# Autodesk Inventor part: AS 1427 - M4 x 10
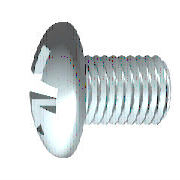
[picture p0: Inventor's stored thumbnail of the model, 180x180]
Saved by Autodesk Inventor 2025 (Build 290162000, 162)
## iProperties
Created: 2024-01
Part Number: AS 1427 - M4 x 10
Material: Acciaio, Dolce
Description: Pozidriv Viti metriche ISO
Document SubType Name: Modeling
Standard: AS 1427
Designer: R5800u
Standards Organization: AS
Language: it-IT
Size Designation: M4 x 10
Categories: <MemberInstance><Categories><Category DisplayName="Elementi di fissaggio" InternalName="e4da775c-781d-43d5-af7c-5136215cf5a6" Mnemonic="FSTN"><Category DisplayN
Density: 7.85 g/cm^3
Appearance: Semilucidato
IsCustomPart: 0
Author: R5800u
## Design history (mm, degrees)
body "Solid1"
workplane "Work Plane3"
sketch "Schizzo2"
  geometry: L1 (-5.6, 0)-(5.6, 0) reference; L2 (0, -5.6)-(0, 5.6) reference; L3 (0, 2.145)-(0, 0); L4 (0, 0)-(2.145, 0); L5 (0, 0)-(2.828, 2.828); L6 (0.495, 2.087)-(0.385, 0.645); L7 (2.087, 0.495)-(0.645, 0.385); L8 (0.495, -2.087)-(0.385, -0.645); L9 (2.087, -0.495)-(0.645, -0.385); L10 (-0.495, 2.087)-(-0.385, 0.645); L11 (-2.087, 0.495)-(-0.645, 0.385); L12 (-2.087, -0.495)-(-0.645, -0.385); L13 (-0.495, -2.087)-(-0.385, -0.645); A1 r 0.644 centre (0, 0) between (0.644, 0) and (0, 0.644); A2 r 2.145 centre (0, 0) between (2.145, 0) and (2.087, 0.495); A3 r 2.145 centre (0, 0) between (0.495, 2.087) and (0, 2.145); A4 r 2.145 centre (0, 0) between (2.087, 0.495) and (0.495, 2.087); A5 r 2.145 centre (0, 0) between (0, -2.145) and (0.495, -2.087); A6 r 2.145 centre (0, 0) between (0.495, -2.087) and (2.087, -0.495); A7 r 2.145 centre (0, 0) between (2.087, -0.495) and (2.145, 0); A8 r 2.145 centre (0, 0) between (-2.087, 0.495) and (-2.145, 0); A9 r 2.145 centre (0, 0) between (-0.495, 2.087) and (-2.087, 0.495); A10 r 2.145 centre (0, 0) between (0, 2.145) and (-0.495, 2.087); A11 r 2.145 centre (0, 0) between (-2.145, 0) and (-2.087, -0.495); A12 r 2.145 centre (0, 0) between (-2.087, -0.495) and (-0.495, -2.087); A13 r 2.145 centre (0, 0) between (-0.495, -2.087) and (0, -2.145); A14 r 0.751 centre (0, 0) between (0.751, 0) and (0, 0.751); A15 r 0.242 centre (0.626, 0.626) between (0.385, 0.645) and (0.645, 0.385); A16 r 0.242 centre (0.626, -0.626) between (0.645, -0.385) and (0.385, -0.645); A17 r 0.242 centre (-0.626, 0.626) between (-0.645, 0.385) and (-0.385, 0.645); A18 r 0.242 centre (-0.626, -0.626) between (-0.385, -0.645) and (-0.645, -0.385); 1 further point
  constraints: 38 point on circle, 22 end point, 19 symmetric about line, 18 centre point, 4 coincident, 3 collinear, 3 point on line, 3 tangent, 1 perpendicular, 21 other
  dimensions: "d4" = 45 deg angle of L5 L4; "d5" = 1.287 diameter of A1 (= 0.3 x SDM); "d6" = 4.29 diameter of A4 (= SDM); "d7" = 0.495 distance from line of L6.start L3 (= 0.5 x SBR); "d14" = 1.5015 diameter of A14 (= 0.35 x SDM)
extrude "Intaglio" join sketch "Schizzo2" taper "d15" = 5 deg; stored distance "d54" = 10
revolve "Taglio" stored, may be unused: angle "d56" = 90 deg
revolve "Corpo" stored, may be unused: angle "d18" = 90 deg
workplane "Work Plane1"
sketch "Schizzo1"
  geometry: L1 (10, 0)-(10, 2); L2 (10, 2)-(1.4, 2); L3 (3.962, 5.08)-(3.962, 5.08); L4 (-2.66, 0)-(-2.66, 4); L5 (-2.334, 1.983)-(-1.654, 1.643); L6 (-1.654, 1.643)-(-0.78, 0); L7 (-0.78, 0)-(10, 0); L8 (-5.617, 0)-(12.603, 0) reference; L9 (0, -1.016)-(0, 6.096) reference; L10 (-2.334, 1.983)-(-2.66, 2.145); L11 (-1.197, 4)-(-2.66, 4); L12 (-1.197, 4)-(0, 4); L13 (0, 4)-(0, 1.785); L14 (0, 1.785)-(0.971, 1.785); L15 (0.971, 1.785)-(1.4, 2); L16 (1.4, 2)-(0, 2); A1 r 6.2 centre (3.54, 0) between (-1.197, 4) and (-2.66, 0)
  constraints: 28 end point, 5 point on line, 4 collinear, 4 point on circle, 3 parallel, 2 perpendicular, 1 centre point, 1 horizontal, 1 tangent
  dimensions: "d1" = 4 diameter of L2 L7 (= GD); "d2" = 1.88 distance from line of L6.end L4 (= STI); "d11" = 4.29 diameter of L10.end L7 (= SDM); "d12" = 62 deg angle of L6 L7; "d13" = 26.5 deg angle of L5 L7; "d17" = 8 diameter of L12.end L7 (= KOD); "d19" = 0.01 deg angle of L12 L7 (= KEWI); "d20" = 2.66 distance between parallel lines of L4 L13 (= KOH); "d21" = 6.2 radius of A1 (= KR); "d23" = 3.5705 diameter of L14 L7 (= BDM); "d24" = 8.6 distance of L1.end L2.end (= GEL); "d25" = 0.42941 horizontal distance of L14.end L2.end (= GAL); "d28" = 10 distance between parallel lines of L1 L13 (= NLG)
fillet "Raccordo1" dims "d29" = 1.6 (= RR)
fillet "Raccordo2" dims "d16" = 0.198 (= 0.2 x SBR)
feature "Filettatura" dims "d8" = 8.6 (= GEL), "d9" = 0
chamfer "Smusso1" distance "d26" = 0.42941 (= -0.5 x SPD + 0.5 x GD); stored, may be unused: second distance "d27" = 0.42952 (computed from GUL), angle "d78" = 45 deg
other parameters: "GD" = 4 (= NND) [user parameter; used in 2 equation terms], "NLG" = 10 [user parameter; used in 1 equation term], "GEL" = 8.6 [user parameter; used in 2 equation terms], "KOD" = 8 [user parameter; used in 1 equation term], "KOH" = 2.66 [user parameter; used in 2 equation terms], "SDM" = 4.29 [user parameter; used in 4 equation terms], "STI" = 1.88 [user parameter; used in 1 equation term], "SBR" = 0.99 [user parameter; used in 2 equation terms], "GAL" = 0.42941 (= 0.61345 x PTC) [user parameter; used in 1 equation term], "SPD" = 3.14117 (= NND - 1.2269 x PTC) [user parameter; used in 1 equation term], "KEWI" = 0.01 deg [user parameter; used in 1 equation term], "d3" = -2.66 (= -KOH), "d10" = 0, "KR" = 6.2 [user parameter; used in 1 equation term], "BDM" = 3.5705 [user parameter; used in 1 equation term], "GUL" = 0.42941 (= 0.61345 x PTC) [user parameter; used in 1 equation term], "RR" = 1.6 [user parameter; used in 1 equation term], "d79" = 0, "d80" = 0, "PTC" = 0.7 [user parameter; used in 5 equation terms], "THREADDIA" = 4 [user parameter; used in 1 equation term], "TOA" = 30 deg [user parameter], "TPU" = 14.28571 (computed from PTC) [user parameter], "NND" = 4 [user parameter; used in 2 equation terms], "GD1" = 3.14117 (= THREADDIA - 1.2269 x PTC) [user parameter]
